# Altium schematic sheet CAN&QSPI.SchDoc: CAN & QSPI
size A4; DocumentNumber: MB1167; Revision: B.1; SheetNumber: 11; SheetTotal: 17; Project: STM327x6G-EVAL
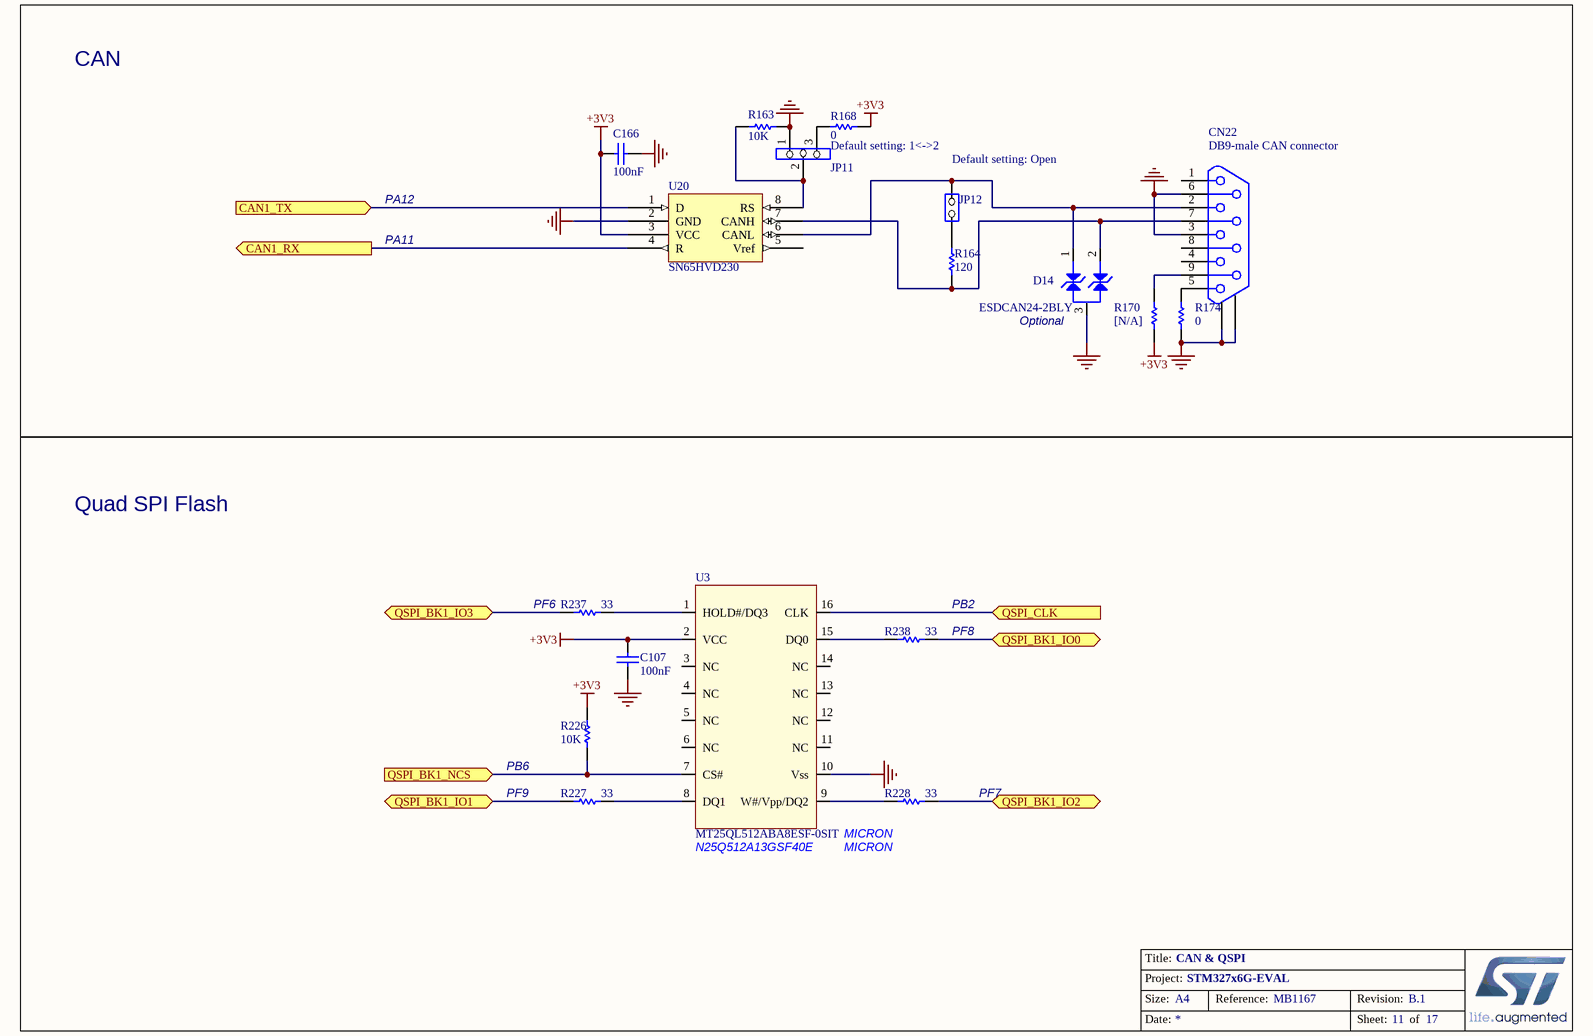
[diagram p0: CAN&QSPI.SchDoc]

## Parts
C107  100nF  [0402C]
C166  100nF  [0603C]
CN22  DB9-male CAN connector  [DB9/M]
D14  ESDCAN24-2BLY  [SOT-23]
JP11  (no value)  [SIP3]
JP12  (no value)  [SIP2]
R163  10K  [0603R]
R164  120  [0603R]
R168  0  [0603R]
R170  [N/A]  [0603R]
R174  0  [0603R]
R226  10K  [0402R]
R227  33  [0603R]
R228  33  [0603R]
R237  33  [0603R]
R238  33  [0603R]
U3  MT25QL512ABA8ESF-0SIT  [SOIC16W_1R27_10R3X10R33]
U20  SN65HVD230  [SOIC8_1R27_4R9X6]

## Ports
CAN1_RX (out), CAN1_TX (in), QSPI_BK1_IO0 (bidir), QSPI_BK1_IO1 (bidir), QSPI_BK1_IO2 (bidir), QSPI_BK1_IO3 (bidir), QSPI_BK1_NCS (in), QSPI_CLK (in)

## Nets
+3V3: C107.1 C166.1 R168.2 R170.1 R226.1 U3.2(VCC) U20.3(VCC)
GND: C107.2 C166.2 CN22.3 CN22.6 CN22.10 CN22.11 D14.3 JP11.1 R163.2 R174.1 U3.10(Vss) U20.2(GND)
CAN1_RX: U20.4(R) ; port CAN1_RX
CAN1_TX: U20.1(D) ; port CAN1_TX
QSPI_BK1_IO0: R238.1 ; port QSPI_BK1_IO0
QSPI_BK1_IO1: R227.2 ; port QSPI_BK1_IO1
QSPI_BK1_IO2: R228.1 ; port QSPI_BK1_IO2
QSPI_BK1_IO3: R237.2 ; port QSPI_BK1_IO3
QSPI_BK1_NCS: R226.2 U3.7(CS#) ; port QSPI_BK1_NCS
QSPI_CLK: U3.16(CLK) ; port QSPI_CLK
NetCN22_2: CN22.2 D14.1 JP12.2(NO) U20.6(CANL)
NetCN22_5: CN22.5 R174.2
NetCN22_7: CN22.7 D14.2 R164.1 U20.7(CANH)
NetCN22_9: CN22.9 R170.2
NetJP11_2: JP11.2 R163.1 U20.8(RS)
NetJP11_3: JP11.3 R168.1
NetJP12_1: JP12.1(COMMON) R164.2
NetR227_1: R227.1 U3.8(DQ1)
NetR228_2: R228.2 U3.9(W#/Vpp/DQ2)
NetR237_1: R237.1 U3.1(HOLD#/DQ3)
NetR238_2: R238.2 U3.15(DQ0)

Not connected (* = marked no-connect by the designer): CN22 1 4 8; U3 3(NC) 4(NC) 5(NC) 6(NC) 11(NC) 12(NC) 13(NC) 14(NC); U20 5(Vref)

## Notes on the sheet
- CAN
- Default setting: 1<->2
- (near JP12) Default setting: Open
- PA12
- PA11
- (near D14) Optional
- Quad SPI Flash
- (near R237) PF6
- (near R238) PF8
- (near R238) PB2
- PB6
- PF9
- (near U3) N25Q512A13GSF40E
- MICRON
- (near R228) PF7

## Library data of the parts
C107 = Cap: Capacitor; Value: 10nF; Ordered by: Subcon
C166 = Cap: Capacitor; Value: 10nF
CN22 = DB9-CAN
JP11 = Jumper3
JP12 = JP2
R163 R227 R228 R237 R238 = Res1: Resistor; Value: 1K
R164 R168 R170 R174 = res1: Resistor; Value: 1K
R226 = res1: Resistor; Value: 1K; Ordered by: Subcon
U3 = QSPI_16pins: ECCN_US/EU: 3A991
U20 = SN65HVD230D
